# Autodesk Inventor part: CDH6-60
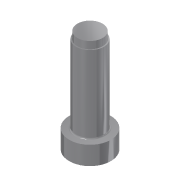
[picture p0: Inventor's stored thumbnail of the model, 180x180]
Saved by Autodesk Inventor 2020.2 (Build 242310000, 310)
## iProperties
Created: 2015-01
Part Number: CDH6-60
Material: Ogólny
Description: Straight Core Pin
Document SubType Name: Modeling
Designer: F.Stasiak
Density: 1 g/cm^3
Appearance: Domyślna
Catalog Web Link: www.expertbooks.pl
Manager: www.cadconsulting.pl
Company: Fabian Stasiak CAD Consulting
Author: F.Stasiak
Subject: Zbiór ćwiczeń. Autodesk Inventor 2020. Kurs Professional
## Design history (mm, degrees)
node "Forma_ZEGAR_260_ZEGAR_260_Rdzeń formujący4_Base"
feature "Solid1::Forma_ZEGAR_260_ZEGAR_260_Rdzeń formujący4_Base"
tag "Bryła wyprowadzona1"
node "Bryła1"
feature "Forma_ZEGAR_260_ZEGAR_260_Rdzeń formujący4_Base_Bodies"
